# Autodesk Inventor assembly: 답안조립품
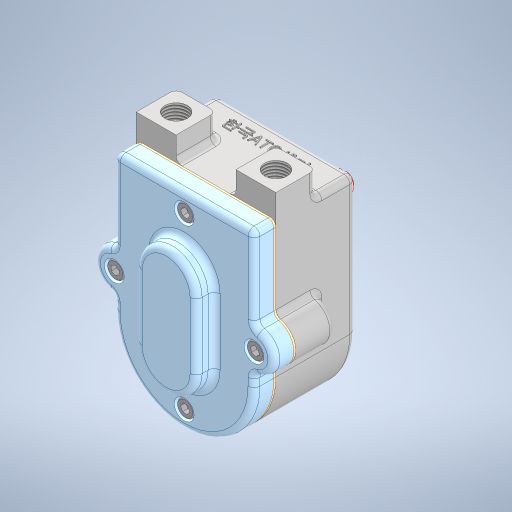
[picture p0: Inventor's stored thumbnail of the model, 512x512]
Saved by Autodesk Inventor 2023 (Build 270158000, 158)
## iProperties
Created: 2024-03
Part Number: 답안조립품
Document SubType Name: Assembly
Designer: asung
Author: asung
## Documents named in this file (9)
- C:\Users\asung\Desktop\740304V1003\답안조립품.iam
- C:\Users\asung\Desktop\740304V1003\본체.ipt
- C:\Users\asung\Desktop\740304V1003\오일 실 14 25 7.ipt
- C:\Users\asung\Desktop\740304V1003\구동기어.ipt
- C:\Users\asung\Desktop\740304V1003\스퍼기어.ipt
- C:\Users\asung\Desktop\740304V1003\가스켓.ipt
- C:\Users\asung\Desktop\740304V1003\커버.ipt
- C:\Users\asung\Desktop\740304V1003\오일레스 부시.ipt
- C:\Users\asung\Desktop\740304V1003\육각 소켓 머리 볼트 M5x12.ipt
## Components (2 placed, 2 different names)
1. 구동기어:1
2. 가스켓:1
